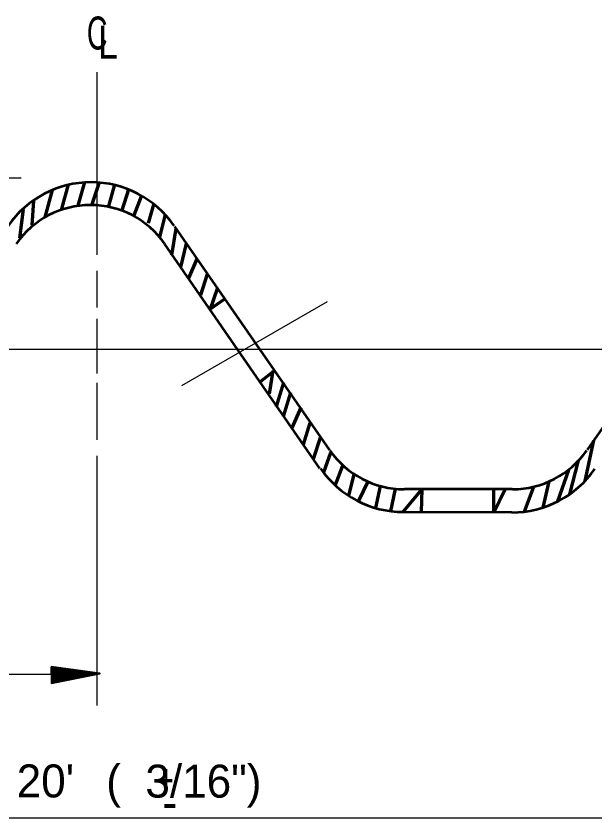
# Model space of a CAD drawing. Extents: x 895.6 to 930.4, y -2278.6 to -2254.7.
# Drawn here: x 903.71 to 905.969, y -2274.643 to -2271.514 of the extents above; entities that cross this region are included whole.
import ezdxf

# ---------------------------------------------------------------- set-up
doc = ezdxf.new("R2010")
doc.units = 0
doc.header["$LTSCALE"] = 0.051
doc.layers.add('1', color=7, linetype='Continuous', lineweight=70)
doc.layers.add('3', color=7, linetype='Continuous', lineweight=40)

msp = doc.modelspace()

# ---------------------------------------------------------------- hatches: boundary and pattern name
at = {"layer": '3'}
for points in [[(903.84717, -2274.05375), (903.84925, -2274.117), (904.03775, -2274.07892), (904.03775, -2274.07892)], [(903.84817, -2274.057), (903.85, -2274.11375), (904.01958, -2274.07958), (904.01958, -2274.07958)], [(903.849, -2274.05975), (903.85067, -2274.11092), (904.00333, -2274.08008), (904.00333, -2274.08008)], [(903.84983, -2274.06233), (903.85133, -2274.10825), (903.98867, -2274.08058), (903.98867, -2274.08058)], [(903.85042, -2274.06442), (903.85192, -2274.10583), (903.9755, -2274.081), (903.9755, -2274.081)], [(903.85125, -2274.06658), (903.85242, -2274.10383), (903.96367, -2274.08133), (903.96367, -2274.08133)], [(903.85167, -2274.06842), (903.85275, -2274.10208), (903.953, -2274.08183), (903.953, -2274.08183)], [(903.85225, -2274.07), (903.85317, -2274.10025), (903.94325, -2274.082), (903.94325, -2274.082)], [(903.85258, -2274.0715), (903.85358, -2274.09883), (903.93467, -2274.0825), (903.93467, -2274.0825)], [(903.85308, -2274.07292), (903.854, -2274.0975), (903.92692, -2274.08258), (903.92692, -2274.08258)], [(903.8535, -2274.07417), (903.85425, -2274.09608), (903.91983, -2274.08292), (903.91983, -2274.08292)], [(903.85375, -2274.07525), (903.8545, -2274.095), (903.91358, -2274.08325), (903.91358, -2274.08325)], [(903.85417, -2274.07617), (903.85467, -2274.09408), (903.90775, -2274.08333), (903.90775, -2274.08333)], [(903.8545, -2274.07717), (903.85492, -2274.09317), (903.90283, -2274.08342), (903.90283, -2274.08342)], [(903.85467, -2274.07792), (903.85517, -2274.09233), (903.89817, -2274.08358), (903.89817, -2274.08358)], [(903.85492, -2274.07858), (903.85525, -2274.09167), (903.89408, -2274.08392), (903.89408, -2274.08392)], [(903.85508, -2274.07925), (903.8555, -2274.09108), (903.89033, -2274.084), (903.89033, -2274.084)], [(903.85525, -2274.07992), (903.85558, -2274.09042), (903.88708, -2274.08408), (903.88708, -2274.08408)], [(903.8555, -2274.08025), (903.85575, -2274.08983), (903.88408, -2274.08408), (903.88408, -2274.08408)], [(903.85567, -2274.08067), (903.85592, -2274.08933), (903.88142, -2274.08408), (903.88142, -2274.08408)], [(903.85583, -2274.081), (903.85608, -2274.08867), (903.879, -2274.084), (903.879, -2274.084)], [(903.85583, -2274.08142), (903.85608, -2274.08833), (903.87683, -2274.08408), (903.87683, -2274.08408)], [(903.856, -2274.08183), (903.85625, -2274.088), (903.87483, -2274.08433), (903.87483, -2274.08433)], [(903.85608, -2274.082), (903.85633, -2274.08758), (903.87308, -2274.08425), (903.87308, -2274.08425)]]:
    msp.add_hatch(color=256, dxfattribs=at).paths.add_polyline_path(points)

# ---------------------------------------------------------------- linework, layer by layer
at = {"layer": '1', "lineweight": 25}
for p, q in [((904.02683, -2272.44575), (904.02683, -2271.73333)), ((901.42708, -2272.14508), (903.73033, -2272.14508)), ((904.02683, -2272.65058), (904.02683, -2272.50808)), ((904.35692, -2272.9555), (904.9255, -2272.62725)), ((904.02683, -2272.90875), (904.02683, -2272.69508)), ((900.56375, -2272.81325), (907.81792, -2272.81325)), ((904.02683, -2273.167), (904.02683, -2272.94442)), ((904.02683, -2274.20475), (904.02683, -2273.22933)), ((900.23575, -2274.08225), (904.02683, -2274.08225)), ((900.23575, -2274.64308), (907.81792, -2274.64308))]:
    msp.add_line(p, q, dxfattribs=at)
at = {"layer": '1'}
for p, q in [((903.88933, -2272.26575), (903.9155, -2272.17158)), ((903.95325, -2272.25317), (903.9785, -2272.16208)), ((904.00733, -2272.24817), (904.03608, -2272.16208)), ((904.0725, -2272.25567), (904.09642, -2272.17158)), ((903.82408, -2272.29842), (903.85242, -2272.19325)), ((904.12392, -2272.27075), (904.14992, -2272.18975)), ((904.1715, -2272.29075), (904.19933, -2272.21642)), ((903.77383, -2272.32975), (903.77958, -2272.23475)), ((904.22683, -2272.32225), (904.24858, -2272.24858)), ((903.72492, -2272.38), (903.73892, -2272.267)), ((904.27192, -2272.37617), (904.293, -2272.2885)), ((904.31842, -2272.44667), (904.335, -2272.343)), ((904.3535, -2272.49425), (904.37533, -2272.40075)), ((904.38492, -2272.53692), (904.41683, -2272.46092)), ((904.43133, -2272.60225), (904.45692, -2272.51958)), ((904.46892, -2272.65642), (904.49692, -2272.57675)), ((904.46525, -2272.65875), (904.5245, -2272.617)), ((904.66375, -2272.93967), (904.71733, -2272.89825)), ((904.69875, -2272.988), (904.71408, -2272.89808)), ((904.72708, -2273.03725), (904.75492, -2272.944)), ((904.75442, -2273.07667), (904.78225, -2272.98325)), ((904.78842, -2273.12042), (904.82292, -2273.04175)), ((904.83208, -2273.18625), (904.85842, -2273.10125)), ((904.8705, -2273.24208), (904.89842, -2273.15892)), ((905.9315, -2273.32692), (905.96458, -2273.17)), ((904.911, -2273.2935), (904.93933, -2273.2175)), ((905.8715, -2273.3795), (905.90558, -2273.2485)), ((904.956, -2273.34508), (904.985, -2273.26717)), ((905.8245, -2273.40717), (905.86775, -2273.28442)), ((905.00892, -2273.38475), (905.02908, -2273.30317)), ((905.04783, -2273.40517), (905.08375, -2273.33)), ((905.11458, -2273.43258), (905.13292, -2273.34842)), ((905.17258, -2273.44592), (905.19158, -2273.35875)), ((905.29183, -2273.45008), (905.29533, -2273.36058)), ((905.69408, -2273.44775), (905.72958, -2273.35367)), ((905.76725, -2273.43108), (905.79, -2273.33025)), ((905.22192, -2273.44692), (905.29392, -2273.36175)), ((905.57425, -2273.45067), (905.61725, -2273.3625)), ((905.5745, -2273.45008), (905.57492, -2273.362))]:
    msp.add_line(p, q, dxfattribs=at)
at = {"layer": '1', "lineweight": 53}
for p, q in [((904.93525, -2273.20842), (904.32975, -2272.33475)), ((906.5425, -2272.33442), (905.93942, -2273.20625)), ((904.89583, -2273.27958), (904.2905, -2272.404)), ((905.646, -2273.35992), (905.22675, -2273.35992)), ((905.64533, -2273.45075), (905.22208, -2273.44917))]:
    msp.add_line(p, q, dxfattribs=at)
for centre, radius, start, end in [((904.00339, -2272.5564), 0.39401, 34.74043, 145.25957), ((904.00094, -2272.60352), 0.3523, 34.73767, 145.26233), ((905.22469, -2273.0079), 0.3523, 214.73767, 270), ((905.64744, -2273.0079), 0.3523, 270, 325.26233), ((905.22223, -2273.05502), 0.39401, 214.73767, 270), ((905.64528, -2273.05675), 0.39401, 270, 325.26233)]:
    msp.add_arc(centre, radius, start, end, dxfattribs=at)
at = {"layer": '3'}
for points in [[(903.84717, -2274.05375), (903.84925, -2274.117), (904.03775, -2274.07892), (904.03775, -2274.07892)], [(903.84817, -2274.057), (903.85, -2274.11375), (904.01958, -2274.07958), (904.01958, -2274.07958)], [(903.849, -2274.05975), (903.85067, -2274.11092), (904.00333, -2274.08008), (904.00333, -2274.08008)], [(903.84983, -2274.06233), (903.85133, -2274.10825), (903.98867, -2274.08058), (903.98867, -2274.08058)], [(903.85042, -2274.06442), (903.85192, -2274.10583), (903.9755, -2274.081), (903.9755, -2274.081)], [(903.85125, -2274.06658), (903.85242, -2274.10383), (903.96367, -2274.08133), (903.96367, -2274.08133)], [(903.85167, -2274.06842), (903.85275, -2274.10208), (903.953, -2274.08183), (903.953, -2274.08183)], [(903.85225, -2274.07), (903.85317, -2274.10025), (903.94325, -2274.082), (903.94325, -2274.082)], [(903.85258, -2274.0715), (903.85358, -2274.09883), (903.93467, -2274.0825), (903.93467, -2274.0825)], [(903.85308, -2274.07292), (903.854, -2274.0975), (903.92692, -2274.08258), (903.92692, -2274.08258)], [(903.8535, -2274.07417), (903.85425, -2274.09608), (903.91983, -2274.08292), (903.91983, -2274.08292)], [(903.85375, -2274.07525), (903.8545, -2274.095), (903.91358, -2274.08325), (903.91358, -2274.08325)], [(903.85417, -2274.07617), (903.85467, -2274.09408), (903.90775, -2274.08333), (903.90775, -2274.08333)], [(903.8545, -2274.07717), (903.85492, -2274.09317), (903.90283, -2274.08342), (903.90283, -2274.08342)], [(903.85467, -2274.07792), (903.85517, -2274.09233), (903.89817, -2274.08358), (903.89817, -2274.08358)], [(903.85492, -2274.07858), (903.85525, -2274.09167), (903.89408, -2274.08392), (903.89408, -2274.08392)], [(903.85508, -2274.07925), (903.8555, -2274.09108), (903.89033, -2274.084), (903.89033, -2274.084)], [(903.85525, -2274.07992), (903.85558, -2274.09042), (903.88708, -2274.08408), (903.88708, -2274.08408)], [(903.8555, -2274.08025), (903.85575, -2274.08983), (903.88408, -2274.08408), (903.88408, -2274.08408)], [(903.85567, -2274.08067), (903.85592, -2274.08933), (903.88142, -2274.08408), (903.88142, -2274.08408)], [(903.85583, -2274.081), (903.85608, -2274.08867), (903.879, -2274.084), (903.879, -2274.084)], [(903.85583, -2274.08142), (903.85608, -2274.08833), (903.87683, -2274.08408), (903.87683, -2274.08408)], [(903.856, -2274.08183), (903.85625, -2274.088), (903.87483, -2274.08433), (903.87483, -2274.08433)], [(903.85608, -2274.082), (903.85633, -2274.08758), (903.87308, -2274.08425), (903.87308, -2274.08425)]]:
    msp.add_lwpolyline(points, close=True, dxfattribs=at)

# ---------------------------------------------------------------- texts
at = {"layer": '1'}
for s, height, width, p in [('C', 0.1287, 0.65, (903.98658, -2271.64433)), ('L', 0.1287, 0.8, (904.03108, -2271.67992)), ('+', 0.1286, 0.55, (904.26908, -2274.55967))]:
    msp.add_text(s, height=height, dxfattribs=dict(at, width=width)).set_placement(p)
for s, p in [("20'", (903.71292, -2274.56283)), (' (  3/16")', (904.0145, -2274.56367)), ('-', (904.28167, -2274.64617))]:
    msp.add_text(s, height=0.1286, dxfattribs=at).set_placement(p)

doc.saveas('drawing.dxf')
